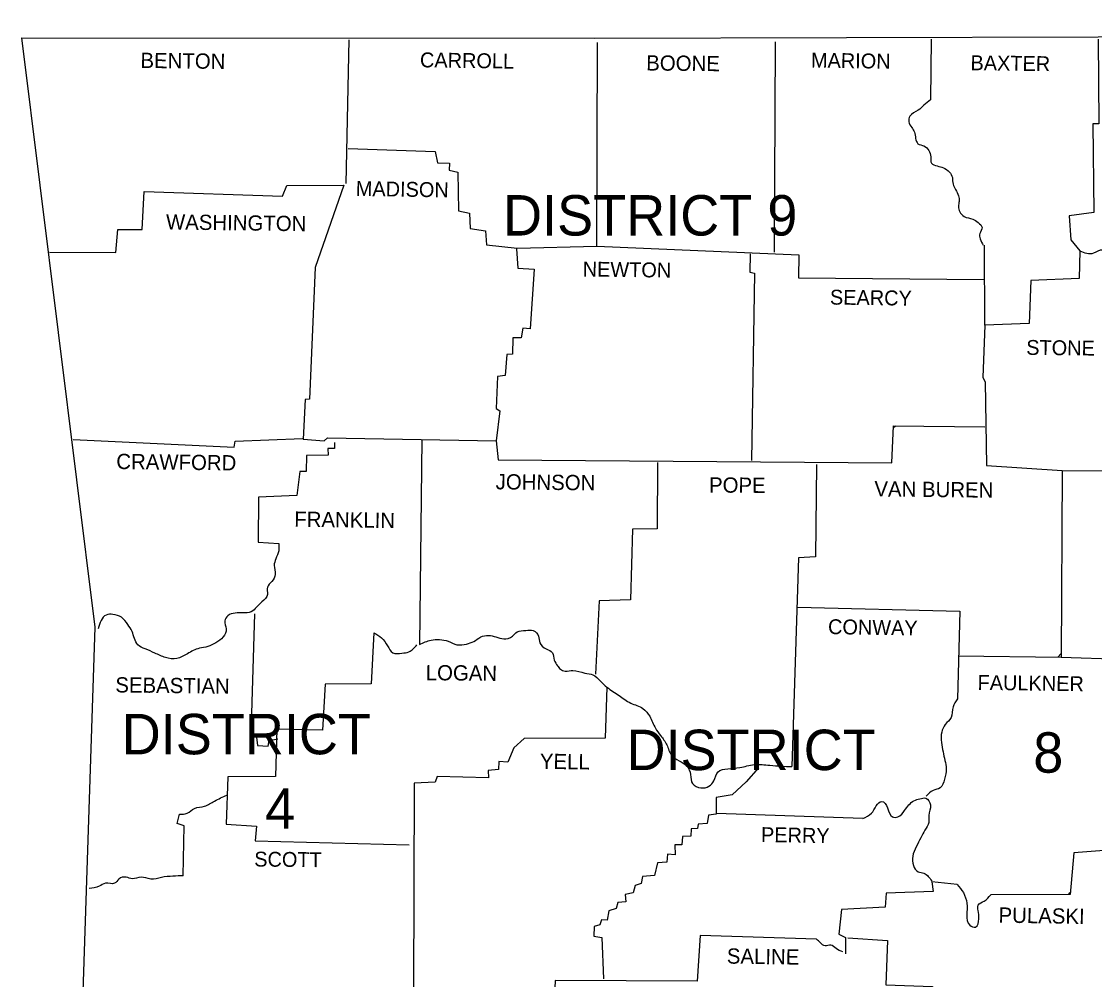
# Model space of a CAD drawing. Extents: x 1334737.7 to 1334827.2, y 402732.3 to 402753.5.
# Drawn here: x 1334820.274 to 1334823.697, y 402750.474 to 402753.53 of the extents above; entities that cross this region are included whole.
import ezdxf

# ---------------------------------------------------------------- set-up
doc = ezdxf.new("R2010")
doc.units = 0
doc.layers.add('Default', color=7, linetype='Continuous')

msp = doc.modelspace()

# ---------------------------------------------------------------- linework, layer by layer
at = {"layer": 'Default'}
for p, q in [((1334823.0553, 402752.2335), (1334823.0619, 402752.2401)), ((1334822.8103, 402752.1243), (1334822.8105, 402752.1245)), ((1334823.0131, 402752.0215), (1334823.0131, 402752.0216)), ((1334823.5799, 402751.502), (1334823.5914, 402751.5136))]:
    msp.add_line(p, q, dxfattribs=at)
for points in [[(1334820.2741, 402753.4772), (1334822.1034, 402753.4762), (1334823.7086, 402753.4803), (1334825.6027, 402753.5091), (1334826.4798, 402753.5297)], [(1334820.2741, 402753.4772), (1334820.5085, 402751.5975), (1334820.4067, 402748.5291)], [(1334821.3188, 402753.471), (1334821.3086, 402753.0124)], [(1334821.3168, 402753.1245), (1334821.5944, 402753.1153), (1334821.6016, 402753.0793), (1334821.6397, 402753.0782), (1334821.6386, 402753.0556), (1334821.6664, 402753.0494), (1334821.6685, 402752.926), (1334821.7034, 402752.9178), (1334821.7055, 402752.8695), (1334821.7548, 402752.8623), (1334821.7579, 402752.817), (1334821.8556, 402752.8068), (1334822.1096, 402752.8129), (1334822.1116, 402753.4628)], [(1334822.6782, 402753.4649), (1334822.6752, 402752.7934)], [(1334823.1759, 402753.4731), (1334823.1739, 402753.2798)], [(1334823.7086, 402753.4731), (1334823.7106, 402753.2037), (1334823.6921, 402753.2027), (1334823.6952, 402752.9209), (1334823.616, 402752.9096), (1334823.6222, 402752.8335), (1334823.65, 402752.7985), (1334823.6479, 402752.7101), (1334823.4937, 402752.7039), (1334823.4885, 402752.5661), (1334823.3477, 402752.561), (1334823.3415, 402752.3944), (1334823.3487, 402752.38), (1334823.3528, 402752.1137), (1334823.5944, 402752.0972), (1334823.5914, 402751.5019), (1334823.7836, 402751.4957), (1334823.7836, 402750.89), (1334823.6315, 402750.8787), (1334823.6201, 402750.745), (1334823.3662, 402750.744)], [(1334820.3636, 402752.7934), (1334820.5754, 402752.7924), (1334820.5816, 402752.8664), (1334820.6587, 402752.8664), (1334820.6659, 402752.9877), (1334821.107, 402752.9723), (1334821.1204, 402753.0063), (1334821.3024, 402753.0073), (1334821.2109, 402752.7451), (1334821.1934, 402752.3255), (1334821.179, 402752.3235), (1334821.1728, 402752.197), (1334821.2397, 402752.1918), (1334821.2499, 402752.2021), (1334821.7888, 402752.1918), (1334821.7949, 402752.1312)], [(1334821.8535, 402752.8047), (1334821.8577, 402752.743), (1334821.9101, 402752.7399), (1334821.8967, 402752.5497), (1334821.8731, 402752.5517), (1334821.8679, 402752.5209), (1334821.8412, 402752.5209), (1334821.8402, 402752.4685), (1334821.8227, 402752.4674), (1334821.8176, 402752.4006), (1334821.7929, 402752.3975), (1334821.7888, 402752.2957), (1334821.8001, 402752.2875), (1334821.7888, 402752.1918)], [(1334822.1096, 402752.8129), (1334822.7543, 402752.7852), (1334822.7533, 402752.7122), (1334823.3446, 402752.707)], [(1334823.3477, 402752.561), (1334823.3466, 402752.816)], [(1334822.5991, 402752.7883), (1334822.598, 402752.7296), (1334822.6124, 402752.7266), (1334822.6032, 402752.1291)], [(1334821.7949, 402752.1312), (1334823.0505, 402752.1219), (1334823.0556, 402752.2402), (1334823.3477, 402752.2371)], [(1334820.4386, 402752.196), (1334820.9528, 402752.1723), (1334820.9559, 402752.1908), (1334821.1708, 402752.2001)], [(1334821.2726, 402752.1867), (1334821.2726, 402752.1672), (1334821.251, 402752.1672), (1334821.252, 402752.1466), (1334821.1831, 402752.1456), (1334821.1821, 402752.0942), (1334821.1625, 402752.0942), (1334821.1523, 402752.0181), (1334821.0299, 402752.0129), (1334821.0289, 402751.869), (1334821.0947, 402751.8649)], [(1334821.5512, 402752.196), (1334821.544, 402751.543)], [(1334822.3029, 402752.123), (1334822.3019, 402751.9111), (1334822.2237, 402751.9101), (1334822.2165, 402751.6849), (1334822.1168, 402751.6818), (1334822.1055, 402751.4484)], [(1334822.8099, 402752.1168), (1334822.8068, 402751.8227), (1334822.7533, 402751.8186), (1334822.7317, 402751.1533)], [(1334823.5944, 402752.0972), (1334824.1754, 402752.0942), (1334824.2258, 402752.1178), (1334824.2227, 402751.6756), (1334824.1878, 402751.6613), (1334824.1579, 402751.6345), (1334824.1477, 402751.6253), (1334824.1466, 402751.4978), (1334823.7764, 402751.4978)], [(1334822.7502, 402751.6613), (1334823.2674, 402751.6489), (1334823.2602, 402751.3692)], [(1334821.0176, 402751.6407), (1334821.0062, 402751.252), (1334821.0237, 402751.2469), (1334821.0268, 402751.2201), (1334821.0607, 402751.2181), (1334821.0638, 402751.2366), (1334821.0916, 402751.2417)], [(1334821.398, 402751.58), (1334821.3898, 402751.4175), (1334821.2427, 402751.4165), (1334821.2345, 402751.2695), (1334821.0885, 402751.2726), (1334821.0844, 402751.1214), (1334820.9322, 402751.1204), (1334820.9271, 402750.9692), (1334821.0237, 402750.963), (1334821.0196, 402750.9168), (1334821.5111, 402750.9034)], [(1334823.2623, 402751.506), (1334823.5914, 402751.5019)], [(1334822.1415, 402751.4062), (1334822.1363, 402751.2438), (1334821.8782, 402751.2427), (1334821.8443, 402751.2129), (1334821.8258, 402751.1677), (1334821.797, 402751.1697), (1334821.796, 402751.144), (1334821.7631, 402751.1409), (1334821.7641, 402751.1173), (1334821.6006, 402751.1214), (1334821.5944, 402751.1039), (1334821.5266, 402751.1008), (1334821.5245, 402750.4396)], [(1334822.6258, 402751.1492), (1334822.5857, 402751.1049), (1334822.5415, 402751.0628), (1334822.4901, 402751.0546), (1334822.4901, 402751.0011), (1334822.4654, 402750.998), (1334822.4613, 402750.9713), (1334822.4325, 402750.9692), (1334822.4304, 402750.9558), (1334822.4109, 402750.9548), (1334822.4099, 402750.9312), (1334822.3831, 402750.9301), (1334822.3811, 402750.9034), (1334822.3584, 402750.9034), (1334822.3595, 402750.8715), (1334822.3348, 402750.8736), (1334822.3327, 402750.8489), (1334822.3029, 402750.8468), (1334822.2937, 402750.8057), (1334822.2556, 402750.8026), (1334822.2515, 402750.78), (1334822.232, 402750.7738), (1334822.2258, 402750.7502), (1334822.2001, 402750.745), (1334822.2021, 402750.7214), (1334822.1764, 402750.7193), (1334822.1713, 402750.7008), (1334822.1476, 402750.6936), (1334822.1425, 402750.6638), (1334822.124, 402750.6648), (1334822.1188, 402750.6484), (1334822.1014, 402750.6432), (1334822.1003, 402750.6124), (1334822.126, 402750.6083), (1334822.1312, 402750.4767)], [(1334820.7903, 402750.8047), (1334820.7934, 402750.9641), (1334820.7708, 402750.9713), (1334820.778, 402751.0011)], [(1334822.9579, 402750.9877), (1334822.4911, 402751.0031)], [(1334823.2592, 402750.7769), (1334823.178, 402750.7852), (1334823.1821, 402750.7553), (1334823.033, 402750.7492), (1334823.0289, 402750.7049), (1334822.8901, 402750.6977), (1334822.8818, 402750.6186), (1334822.9024, 402750.6083), (1334822.9024, 402750.5558)], [(1334823.615, 402750.7461), (1334823.6201, 402750.7512)], [(1334822.8099, 402750.6031), (1334822.4397, 402750.6145), (1334822.4294, 402750.4684), (1334821.9769, 402750.4715), (1334821.9749, 402750.4222)], [(1334822.9106, 402750.6073), (1334823.0371, 402750.599), (1334823.032, 402750.4571), (1334823.18, 402750.452), (1334823.1831, 402750.3286), (1334823.253, 402750.3224), (1334823.253, 402750.3019), (1334823.3189, 402750.2967), (1334823.3209, 402750.2175), (1334823.47, 402750.2175), (1334823.4741, 402750.1394), (1334823.6129, 402750.1332), (1334823.6119, 402749.9862)]]:
    msp.add_lwpolyline(points, dxfattribs=at)
for points in [[(1334823.1739, 402753.2798), (1334823.1533, 402753.2623), (1334823.1348, 402753.2469), (1334823.1081, 402753.2273), (1334823.105, 402753.2099), (1334823.1142, 402753.1913), (1334823.1225, 402753.177), (1334823.1266, 402753.1564), (1334823.1338, 402753.1399), (1334823.1533, 402753.1327), (1334823.1687, 402753.1183), (1334823.1749, 402753.0978), (1334823.177, 402753.0782), (1334823.1955, 402753.069), (1334823.215, 402753.0628), (1334823.2345, 402753.0494), (1334823.2438, 402753.032), (1334823.2459, 402753.0104), (1334823.2541, 402752.9939), (1334823.2633, 402752.9733), (1334823.2654, 402752.9559), (1334823.2633, 402752.9394), (1334823.2674, 402752.923), (1334823.2818, 402752.9075), (1334823.3086, 402752.8993), (1334823.3261, 402752.888), (1334823.3384, 402752.8726), (1334823.3312, 402752.853), (1334823.3322, 402752.8366), (1334823.3425, 402752.816)], [(1334823.65, 402752.7985), (1334823.6952, 402752.7913), (1334823.7219, 402752.8016), (1334823.7415, 402752.7718), (1334823.7518, 402752.7492), (1334823.7682, 402752.7163), (1334823.796, 402752.706), (1334823.8166, 402752.6885), (1334823.8166, 402752.669), (1334823.798, 402752.6505), (1334823.7847, 402752.633), (1334823.7888, 402752.6114), (1334823.7939, 402752.5816), (1334823.7939, 402752.5538), (1334823.7867, 402752.5271), (1334823.7806, 402752.5034), (1334823.7867, 402752.4839), (1334823.8083, 402752.487), (1334823.8309, 402752.5034), (1334823.8546, 402752.5034), (1334823.8772, 402752.4911), (1334823.9009, 402752.4695), (1334823.9245, 402752.4746), (1334823.9441, 402752.4798), (1334823.9708, 402752.488), (1334823.9903, 402752.4777), (1334824.0068, 402752.4643), (1334824.0273, 402752.4428), (1334824.0469, 402752.4294), (1334824.0716, 402752.417), (1334824.1024, 402752.4088), (1334824.1302, 402752.3893), (1334824.1353, 402752.3564), (1334824.1343, 402752.3286), (1334824.1322, 402752.2936), (1334824.1292, 402752.2546), (1334824.1333, 402752.2176), (1334824.1456, 402752.1929), (1334824.161, 402752.1631), (1334824.1651, 402752.1363), (1334824.1641, 402752.0931)], [(1334821.0947, 402751.8649), (1334821.0947, 402751.8412), (1334821.0854, 402751.8155), (1334821.0803, 402751.7949), (1334821.0834, 402751.7661), (1334821.0731, 402751.7435), (1334821.0587, 402751.725), (1334821.0587, 402751.7024), (1334821.0412, 402751.6787), (1334821.0237, 402751.6613), (1334821.0073, 402751.6469), (1334820.9795, 402751.6438), (1334820.9559, 402751.6427), (1334820.9322, 402751.6345), (1334820.9229, 402751.6181), (1334820.9271, 402751.5924), (1334820.9178, 402751.5666), (1334820.8942, 402751.5481), (1334820.8684, 402751.5358), (1334820.8417, 402751.5307), (1334820.8037, 402751.5132), (1334820.7697, 402751.4978), (1334820.7337, 402751.5008), (1334820.6998, 402751.5152), (1334820.669, 402751.5286), (1334820.6453, 402751.542), (1334820.6268, 402751.5841), (1334820.6134, 402751.6068), (1334820.5929, 402751.6294), (1334820.5661, 402751.6386), (1334820.5445, 402751.6366), (1334820.5188, 402751.5924)], [(1334821.398, 402751.58), (1334821.4227, 402751.5636), (1334821.4422, 402751.5379), (1334821.4587, 402751.5163), (1334821.4875, 402751.5152), (1334821.5101, 402751.5193), (1334821.5358, 402751.542)], [(1334821.544, 402751.543), (1334821.5811, 402751.5564), (1334821.6078, 402751.5584), (1334821.6356, 402751.5533), (1334821.6633, 402751.542), (1334821.6942, 402751.544), (1334821.7168, 402751.5523), (1334821.7394, 402751.5666), (1334821.7641, 402751.5718), (1334821.7877, 402751.5666), (1334821.8124, 402751.5605), (1334821.8402, 402751.5687), (1334821.8556, 402751.5831), (1334821.8834, 402751.5872), (1334821.907, 402751.5872), (1334821.9235, 402751.5687), (1334821.9276, 402751.5481), (1334821.9482, 402751.5286), (1334821.9677, 402751.5163), (1334821.9739, 402751.4926), (1334821.9841, 402751.4751), (1334821.9934, 402751.4638), (1334822.0088, 402751.4577), (1334822.0335, 402751.4597), (1334822.0715, 402751.4515), (1334822.0973, 402751.4463), (1334822.1199, 402751.4268), (1334822.1415, 402751.4062)], [(1334822.1415, 402751.4062), (1334822.1805, 402751.3795), (1334822.2176, 402751.3559), (1334822.2566, 402751.3384), (1334822.2782, 402751.3137), (1334822.2967, 402751.2756), (1334822.3132, 402751.252), (1334822.3327, 402751.2222), (1334822.3482, 402751.1893), (1334822.3718, 402751.1718), (1334822.3965, 402751.1553), (1334822.4088, 402751.1276), (1334822.415, 402751.0988), (1334822.4417, 402751.0854), (1334822.4674, 402751.0906), (1334822.4829, 402751.108), (1334822.4962, 402751.1368), (1334822.5271, 402751.1461), (1334822.5662, 402751.1502), (1334822.6114, 402751.1594), (1334822.6618, 402751.1574), (1334822.7317, 402751.1533)], [(1334823.2602, 402751.3692), (1334823.2459, 402751.3435), (1334823.2397, 402751.3096), (1334823.2212, 402751.288), (1334823.2099, 402751.2633), (1334823.2088, 402751.2304), (1334823.214, 402751.2006), (1334823.2201, 402751.1728), (1334823.2243, 402751.1461), (1334823.2191, 402751.1132), (1334823.2047, 402751.0854), (1334823.1821, 402751.0772), (1334823.1605, 402751.0587)], [(1334820.778, 402751.0011), (1334820.8026, 402751.0042), (1334820.8263, 402751.0196), (1334820.8582, 402751.0268), (1334820.89, 402751.0433), (1334820.9291, 402751.0618)], [(1334822.9579, 402750.9877), (1334822.9857, 402751.0042), (1334823.0011, 402751.0278), (1334823.0186, 402751.0422), (1334823.0371, 402751.0217), (1334823.0525, 402750.9929), (1334823.07, 402750.9929), (1334823.0916, 402751.0134), (1334823.105, 402751.0309), (1334823.1214, 402751.0443), (1334823.1399, 402751.0504), (1334823.1595, 402751.0525), (1334823.1739, 402751.0309), (1334823.1687, 402750.997), (1334823.1687, 402750.9744), (1334823.1564, 402750.9507), (1334823.143, 402750.926), (1334823.1286, 402750.8972), (1334823.1173, 402750.8674), (1334823.1194, 402750.8376), (1334823.1348, 402750.8181), (1334823.1533, 402750.8129), (1334823.178, 402750.7882)], [(1334820.7903, 402750.8047), (1334820.7574, 402750.8037), (1334820.7204, 402750.7995), (1334820.6864, 402750.7944), (1334820.6556, 402750.8006), (1334820.6278, 402750.7954), (1334820.6083, 402750.8006), (1334820.5846, 402750.7944), (1334820.5713, 402750.781), (1334820.5425, 402750.781), (1334820.5219, 402750.7718), (1334820.49, 402750.7646)], [(1334823.2592, 402750.7769), (1334823.2788, 402750.7512), (1334823.2901, 402750.7173), (1334823.2901, 402750.6792), (1334823.2993, 402750.6474), (1334823.3178, 402750.6412), (1334823.3281, 402750.6679), (1334823.3261, 402750.6947), (1334823.3261, 402750.7111), (1334823.3456, 402750.7245), (1334823.3662, 402750.744)], [(1334822.8942, 402750.562), (1334822.8726, 402750.5733), (1334822.8561, 402750.5836), (1334822.8376, 402750.5816), (1334822.8232, 402750.5908), (1334822.8099, 402750.6031)]]:
    msp.add_spline(points, degree=3, dxfattribs=at)

# ---------------------------------------------------------------- texts
for s, height, rotation, p in [('BENTON', 0.04864, 359.2527, (1334820.6535, 402753.3816)), ('CARROLL', 0.04751, 359.1481, (1334821.5451, 402753.3836)), ('BOONE', 0.04864, 359.4001, (1334822.2669, 402753.3734)), ('MARION', 0.04751, 359.1854, (1334822.7924, 402753.3826)), ('BAXTER', 0.04751, 359.2559, (1334823.3014, 402753.3744)), ('MADISON', 0.04751, 359.0906, (1334821.3404, 402752.9733)), ('WASHINGTON', 0.04863, 359.232, (1334820.7348, 402752.8664)), ('NEWTON', 0.04751, 359.2717, (1334822.0643, 402752.7163)), ('SEARCY', 0.04749, 359.2527, (1334822.853, 402752.6268)), ('STONE', 0.04749, 359.4001, (1334823.4793, 402752.4664)), ('CRAWFORD', 0.04863, 359.2771, (1334820.5764, 402752.1024)), ('JOHNSON', 0.04864, 359.3514, (1334821.7867, 402752.0376)), ('POPE', 0.04864, 359.6155, (1334822.4674, 402752.0273)), ('VAN BUREN', 0.04864, 359.3508, (1334822.9949, 402752.015)), ('FRANKLIN', 0.04864, 359.1815, (1334821.144, 402751.9183)), ('CONWAY', 0.04749, 359.0371, (1334822.8469, 402751.5759)), ('LOGAN', 0.04864, 359.3969, (1334821.5636, 402751.4289)), ('SEBASTIAN', 0.04863, 359.2816, (1334820.5733, 402751.3898)), ('FAULKNER', 0.04751, 359.2486, (1334823.324, 402751.398)), ('YELL', 0.04864, 359.1987, (1334821.9276, 402751.1461)), ('PERRY', 0.04751, 359.0858, (1334822.633, 402750.9127)), ('SCOTT', 0.04751, 359.4063, (1334821.0165, 402750.8345)), ('PULASKI', 0.04864, 359.053, (1334823.3908, 402750.6556)), ('SALINE', 0.04864, 359.1491, (1334822.524, 402750.525))]:
    msp.add_text(s, height=height, rotation=rotation, dxfattribs=at).set_placement(p)
for s, height, p in [('DISTRICT 9', 0.12895, (1334821.8104, 402752.8469)), ('DISTRICT', 0.12895, (1334820.5939, 402751.1924)), ('DISTRICT', 0.12895, (1334822.2042, 402751.142)), ('8', 0.1289, (1334823.5019, 402751.1337)), ('4', 0.1289, (1334821.0515, 402750.9548))]:
    msp.add_text(s, height=height, dxfattribs=at).set_placement(p)

doc.saveas('drawing.dxf')
